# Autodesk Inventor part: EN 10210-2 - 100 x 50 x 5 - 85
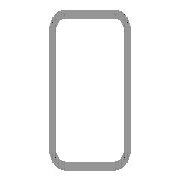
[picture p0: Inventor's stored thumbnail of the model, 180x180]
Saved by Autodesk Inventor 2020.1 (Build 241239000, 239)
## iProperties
Created: 2019-01
Part Number: EN 10210-2 - 100 x 50 x 5 - 85
Material: Steel, Mild
Description: Rohrleitung
Document SubType Name: Modeling
Standard: DIN
Designer: lutzd
Standard Revision: 2006-07
Standards Organization: DIN
Language: de-DE
Size Designation: 100 x 50 x 5
Categories: <MemberInstance><Categories><Category DisplayName="Profile" InternalName="089c4875-fa83-4c05-b084-43b9cc11f5ed" Mnemonic="GRDR"><CategoryParameter DisplayName="
Stock Number: 100 x 50 x 5
Mass: 116.72 g
Surface Area: 485.222 cm^2
Volume: 116.72 cm^3
Density: 1 g/cm^3
Appearance: Semi-Polished
_CCFamilyMember: 159
_CCFamilyDisplayName: DIN EN 10210-2 (USAS B17.1 rechteckig) - Rohrleitung — In Klammern angegebene Größen wurden aufgehoben
_FrameMemberDoc: Frame Member File
_Version: 15.0.0
_GetPNFromCC: 1
G_W: 50,000 mm
G_H: 100,000 mm
+522F6094-0B18-4E5E-8924-1483E42E42DB+SCHNITTDETAIL1: Schnittwinkel 90,00 grd
DocNumber: ADSK-014240
Folder: .
Dimensions: 50x100x85 mm
Mass: 0,117 kg
G_L: 85,000 mm
IsCustomPart: 1
Title: Profil-Bauteil
Author: lutzd
Revision Number: -
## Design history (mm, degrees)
node "Startebene"
node "Endebene"
sketch "Skizze"
  geometry: L1 (-25, -42.5)-(-25, 42.5); L2 (-17.5, 50)-(17.5, 50); L3 (25, 42.5)-(25, -42.5); L4 (17.5, -50)-(-17.5, -50); L5 (-15, 45)-(15, 45); L6 (20, 40)-(20, -40); L7 (15, -45)-(-15, -45); L8 (-20, -40)-(-20, 40); L9 (0, 72.175)-(0, -72.175) reference; L10 (-37.175, 0)-(37.175, 0) reference; A1 r 7.5 centre (-17.5, -42.5) between (-25, -42.5) and (-17.5, -50); A2 r 7.5 centre (-17.5, 42.5) between (-17.5, 50) and (-25, 42.5); A3 r 7.5 centre (17.5, 42.5) between (25, 42.5) and (17.5, 50); A4 r 7.5 centre (17.5, -42.5) between (17.5, -50) and (25, -42.5); A5 r 5 centre (-15, -40) between (-20, -40) and (-15, -45); A6 r 5 centre (-15, 40) between (-15, 45) and (-20, 40); A7 r 5 centre (15, 40) between (20, 40) and (15, 45); A8 r 5 centre (15, -40) between (15, -45) and (20, -40)
  constraints: 16 end point, 16 point on circle, 16 tangent, 8 centre point, 6 equal radius, 4 parallel, 2 perpendicular, 2 other
  dimensions: "d7" = 7.5 radius of A1 (= G_IR); "d10" = 100 distance between parallel lines of L2 L4 (= G_H); "d11" = 50 distance between parallel lines of L1 L3 (= G_W); "d12" = 5 distance between parallel lines of L3 L6 (= G_T); "d15" = 50 distance between parallel lines of L2 L10 (= 0.5 x d10); "d16" = 25 distance between parallel lines of L9 L3 (= 0.5 x d11); "d19" = 5 radius of A5 (= G_T); "d20" = 5 distance between parallel lines of L4 L7 (= G_T)
extrude "Körper" new body sketch "Skizze" stored distance "d3" = 85 (= G_L); taper "d4" = 0 deg
node "Driven Length"
  sketch "Sketch3"
    geometry: L1 (0, 0)-(10, 0) reference
    constraints: 2 end point, 1 horizontal
  workplane "Work Plane3"
  sketch "Sketch4"
    geometry: L1 (-2, 50)-(12, 50) reference; L2 (-2, 135)-(12, 135) reference
    dimensions: "d18" = 85 distance between parallel lines of L1 L2 (derived)
workplane "Arbeitsebene4"
feature "Trennen1"
body "Solid1"
other parameters: "G_W" = 50 [user parameter; used in 1 equation term], "G_H" = 100 [user parameter; used in 1 equation term], "G_T" = 5 [user parameter; used in 3 equation terms], "G_IR" = 7.5 [user parameter; used in 1 equation term], "G_L" = 85 (= d18) [user parameter; used in 1 equation term], "G_OFFSET_END" = 0 [user parameter; used in 1 equation term], "d14" = 135 (= G_OFFSET_END + B_L), "B_L" = 135 [user parameter; used in 1 equation term], "d17" = 90 deg
